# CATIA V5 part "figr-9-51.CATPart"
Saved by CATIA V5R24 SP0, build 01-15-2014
Part number: Part1
Bounding box of the stored display mesh (mm): x -121 to 121, y -90 to 90, z -40 to 40
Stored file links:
  D:\KAVITA\CATIA V5-6R2014 Project_ Kavita\CATIA V5-6R2014_partfiles\Partfiles\c09_catia_v5-6r2014_prt\figr-9-51.CATPart
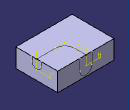
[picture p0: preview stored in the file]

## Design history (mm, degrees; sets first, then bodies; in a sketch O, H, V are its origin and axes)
Body1 (main body)
  Sketch1 on yz-plane, origin (0, 0, 0), H (0, 1, 0), V (0, 0, 1)
    line L1 (-90, 40) -> (90, 40)
    line L2 (90, 40) -> (90, -40)
    line L3 (90, -40) -> (-90, -40)
    line L4 (-90, -40) -> (-90, 40)
    axis line L5 (90, -40) -> (-90, 40)
    horizontal: L1 H, L3 H
    vertical: L2 V, L4 V
    midpoint: O L5
  Pad1: profile Sketch1, direction (1, 0, 0), length 121, mirrored extent
  Sketch2 on face of Pad1, origin (0, 0, 40), H (1, 0, 0), V (0, 1, 0)
    point P1 (121, 0)
    line L1 (121, 0) -> (40.984, 0)
    arc A1 centre (40.984, 40.984) radius 40.984 from (40.984, 0) to (0, 40.984) cw
    line L2 (0, 40.984) -> (0, 90)
    point P5 (0, 90)
    reference projected line E1 (121, 20) -> (121, -20) from edge of Sketch4
    reference projected line E2 (-25.9516, 90) -> (25.9516, 90) from edge of Sketch3
    coincidence: P1 H, P1 E1, P5 E2
    horizontal: L1 H
    tangency: A1 L1, L2 A1
    vertical: L2 V
  Sketch3 on face of Pad1, origin (0, 90, 0), H (-1, 0, 0), V (0, 0, 1)
    line L1 (-25.9516, 40) -> (-25.9516, -8.0968)
    arc A1 centre (0, -8.0968) radius 25.9516 from (-25.9516, -8.0968) to (25.9516, -8.0968) ccw
    point P3 (0, -8.0968)
    line L2 (25.9516, -8.0968) -> (25.9516, 40)
    line L3 (25.9516, 40) -> (-25.9516, 40)
    reference projected line E1 (121, 40) -> (-121, 40) from edge [face of Pad1 | face of Pad1]
    vertical: L1 V, L2 V
    tangency: A1 L1, L2 A1
    horizontal: L3 H
    coincidence: P3 V, L3 E1
  Sketch4 on face of Pad1, origin (121, 0, 0), H (0, 1, 0), V (0, 0, 1)
    line L1 (-20, 40) -> (-20, 21.9917)
    arc A1 centre (0, 21.9917) radius 20 from (-20, 21.9917) to (20, 21.9917) ccw
    point P3 (0, 21.9917)
    line L2 (20, 21.9917) -> (20, 40)
    line L3 (20, 40) -> (-20, 40)
    reference projected line E1 (90, 40) -> (-90, 40) from edge [face of Pad1 | face of Pad1]
    vertical: L1 V, L2 V
    tangency: A1 L1, L2 A1
    horizontal: L3 H
    coincidence: P3 V, L3 E1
